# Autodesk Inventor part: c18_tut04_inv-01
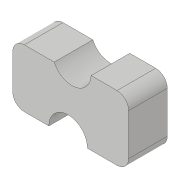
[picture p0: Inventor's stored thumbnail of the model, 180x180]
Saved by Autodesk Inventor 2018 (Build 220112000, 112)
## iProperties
Created: 2017-06
Part Number: c18_tut04_inv-01
Material: Generic
Document SubType Name: Modeling
Designer: CADCIM 00
Density: 1 g/cm^3
Appearance: Default
Author: CADCIM 00
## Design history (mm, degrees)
sketch "Sketch1"
  geometry: L1 (-60, 0)-(-60, 33.532); L2 (0, 30)-(0, 0); L3 (-60, 33.532)-(-40.6, 33.532); L4 (-21.474, 30)-(0, 30); L5 (0, 0)-(-18.704, 0); L6 (-38.704, 0)-(-60, 0); A1 r 10 centre (-30.614, 34.057) between (-40.6, 33.532) and (-21.474, 30); A2 r 10 centre (-28.704, 0) between (-18.704, 0) and (-38.704, 0)
  constraints: 12 end point, 5 parallel, 4 point on circle, 2 centre point, 2 horizontal, 2 perpendicular, 1 equal radius
  dimensions: "d0" = 60 distance between parallel lines of L1 L2 (= LEN); "d1" = 30 distance of L2.start L2.end (= WID); "d2" = 10 radius of A2 (= RAD)
extrude "Extrusion1" new body sketch "Sketch1" distance "d3" = 20 (= EXT); taper "d4" = 0 deg
fillet "Fillet1" dims "d5" = 6 (= FILLET)
body "Solid1"
other parameters: "LEN" = 60 [user parameter; used in 5 equation terms], "WID" = 30 (= 0.5 x LEN) [user parameter; used in 1 equation term], "RAD" = 10 (= 0.166667 x LEN) [user parameter; used in 1 equation term], "EXT" = 20 (= 0.333333 x LEN) [user parameter; used in 1 equation term], "FILLET" = 6 (= 0.1 x LEN) [user parameter; used in 1 equation term]
